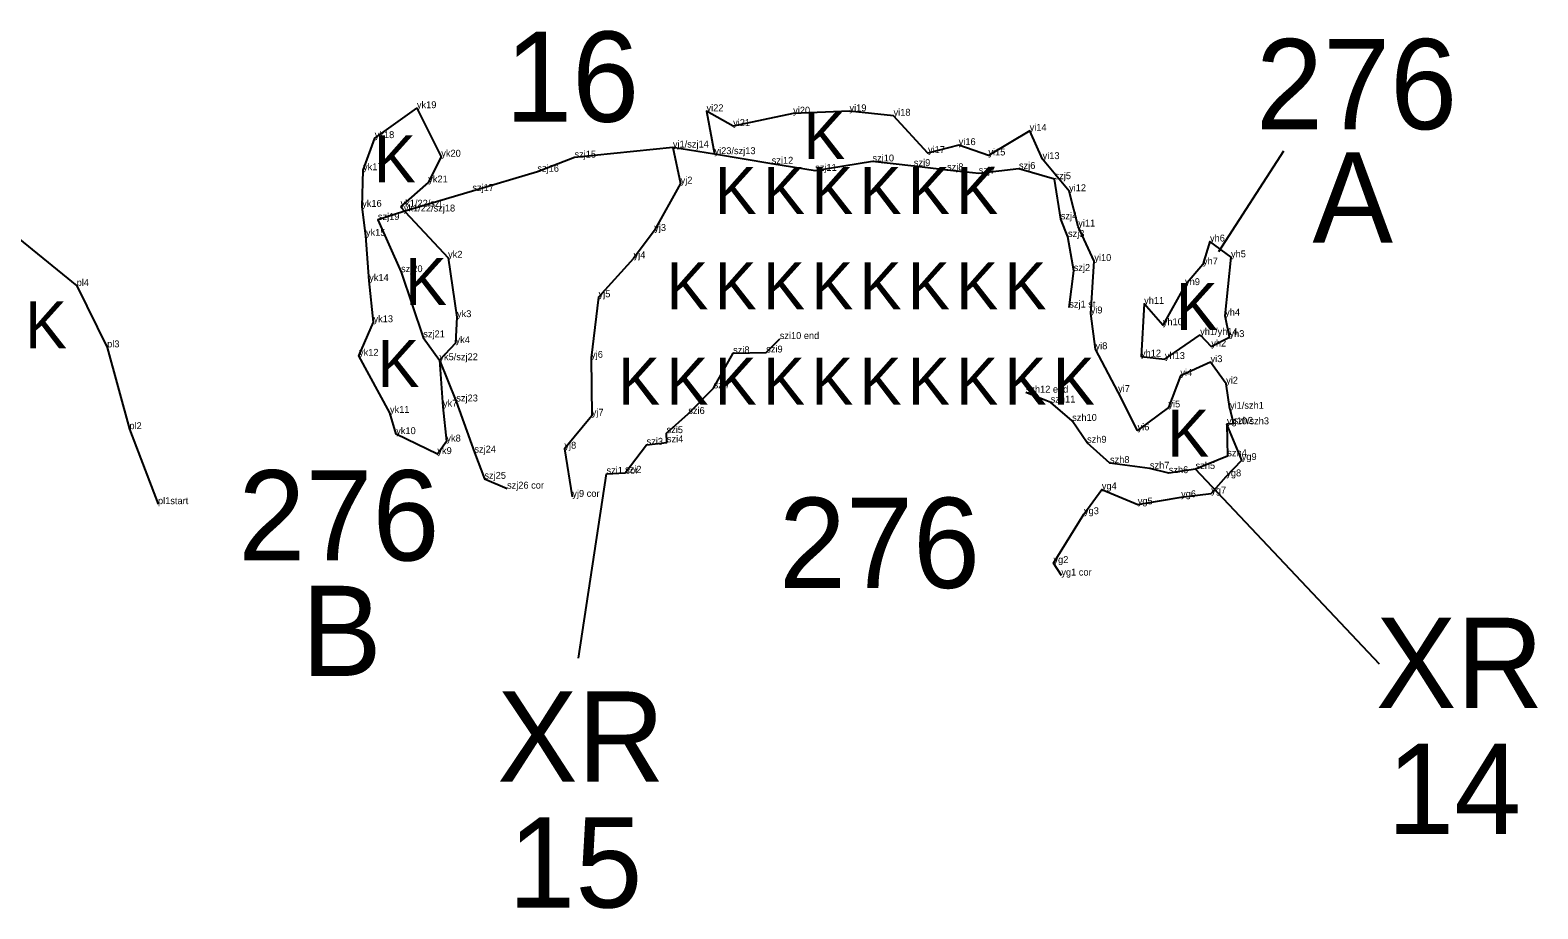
# Model space of a CAD drawing. Extents: x 2072529 to 2268812, y 436423 to 470008.
# Drawn here: x 2234269 to 2235362, y 437440 to 438077 of the extents above; entities that cross this region are included whole.
import ezdxf

# ---------------------------------------------------------------- set-up
doc = ezdxf.new("R2010")
doc.units = 0
for name, color, linetype in [('Old_Level_10', 7, 'Continuous'), ('Old_Level_20', 7, 'Continuous'), ('Old_Level_52', 7, 'Continuous'), ('Old_Level_55', 7, 'Continuous'), ('Old_Level_60', 7, 'Continuous'), ('Old_Level_62', 7, 'Continuous')]:
    doc.layers.add(name, color=color, linetype=linetype)

msp = doc.modelspace()

# ---------------------------------------------------------------- linework, layer by layer
at = {"layer": 'Old_Level_10'}
for points in [[(2235022.15, 437875.772), (2235025.327, 437902.254), (2235021.192, 437926.912), (2235015.992, 437939.663), (2235011.459, 437968.738), (2234985.669, 437976.204), (2234956.556, 437972.832), (2234933.554, 437975.202), (2234909.517, 437978.237), (2234879.528, 437981.569), (2234838.013, 437974.72), (2234806.501, 437979.899), (2234765.07, 437986.858), (2234734.927, 437991.638), (2234663.634, 437984.333)], [(2234663.634, 437984.333), (2234636.744, 437974.103), (2234589.636, 437960.148), (2234539.989, 437945.334), (2234521.191, 437939.225), (2234537.967, 437901.417), (2234537.967, 437901.417), (2234554.11, 437854.212), (2234565.741, 437837.655), (2234578.009, 437807.788), (2234591.124, 437770.801), (2234598.353, 437751.778), (2234614.765, 437744.67)], [(2234686.83, 437755.439), (2234700.252, 437756.17), (2234715.876, 437776.426), (2234730.592, 437778.188), (2234730.315, 437784.863), (2234746.096, 437798.752), (2234764.454, 437817.355), (2234778.551, 437842.644), (2234802.551, 437843.25), (2234812.336, 437853.021)], [(2235138.563, 437802.471), (2235141.179, 437791.607), (2235136.336, 437791.232), (2235136.644, 437768.164), (2235113.636, 437758.868), (2235094.216, 437755.875), (2235080.539, 437759.128), (2235051.628, 437763.196), (2235034.996, 437777.892), (2235024.223, 437793.719), (2235008.663, 437806.995), (2234990.571, 437814.172)]]:
    msp.add_lwpolyline(points, dxfattribs=at)
at = {"layer": 'Old_Level_20'}
for p, q in [((2234549.462, 438020.14), (2234549.462, 438020.14)), ((2234759.309, 438017.899), (2234759.309, 438017.899)), ((2234822.071, 438016.169), (2234822.071, 438016.169)), ((2234862.899, 438017.892), (2234862.899, 438017.892)), ((2234894.802, 438014.665), (2234894.802, 438014.665)), ((2234518.925, 437998.451), (2234518.925, 437998.451)), ((2234778.554, 438007.23), (2234778.554, 438007.23)), ((2234993.448, 438003.763), (2234993.448, 438003.763)), ((2234734.927, 437991.638), (2234734.927, 437991.638)), ((2234765.07, 437986.858), (2234765.07, 437986.858)), ((2234919.763, 437987.653), (2234919.763, 437987.653)), ((2234942.011, 437993.39), (2234942.011, 437993.39)), ((2234567.121, 437985.001), (2234567.121, 437985.001)), ((2234663.634, 437984.333), (2234663.634, 437984.333)), ((2234806.501, 437979.899), (2234806.501, 437979.899)), ((2234879.528, 437981.569), (2234879.528, 437981.569)), ((2234909.517, 437978.237), (2234909.517, 437978.237)), ((2234963.543, 437985.902), (2234963.543, 437985.902)), ((2234985.669, 437976.204), (2234985.669, 437976.204)), ((2235002.799, 437983.256), (2235002.799, 437983.256)), ((2234510.467, 437975.219), (2234510.467, 437975.219)), ((2234557.684, 437966.361), (2234557.684, 437966.361)), ((2234636.744, 437974.103), (2234636.744, 437974.103)), ((2234740.535, 437965.54), (2234740.535, 437965.54)), ((2234838.013, 437974.72), (2234838.013, 437974.72)), ((2234933.554, 437975.202), (2234933.554, 437975.202)), ((2234956.556, 437972.832), (2234956.556, 437972.832)), ((2235011.459, 437968.738), (2235011.459, 437968.738)), ((2234589.636, 437960.148), (2234589.636, 437960.148)), ((2235021.981, 437959.999), (2235021.981, 437959.999)), ((2234509.818, 437948.702), (2234509.818, 437948.702)), ((2234537.63, 437948.816), (2234537.63, 437948.816)), ((2234539.989, 437945.334), (2234539.989, 437945.334)), ((2234521.191, 437939.225), (2234521.191, 437939.225)), ((2235015.992, 437939.663), (2235015.992, 437939.663)), ((2235028.621, 437934.464), (2235028.621, 437934.464)), ((2234512.538, 437927.728), (2234512.538, 437927.728)), ((2234721.404, 437931.218), (2234721.404, 437931.218)), ((2235021.192, 437926.912), (2235021.192, 437926.912)), ((2235124.081, 437923.587), (2235124.081, 437923.587)), ((2234572.047, 437911.831), (2234572.047, 437911.831)), ((2234706.445, 437911.397), (2234706.445, 437911.397)), ((2235139.3, 437912.147), (2235139.3, 437912.147)), ((2234537.967, 437901.417), (2234537.967, 437901.417)), ((2235025.327, 437902.254), (2235025.327, 437902.254)), ((2235040.267, 437909.469), (2235040.267, 437909.469)), ((2235118.998, 437906.971), (2235118.998, 437906.971)), ((2234302.955, 437891.465), (2234302.955, 437891.465)), ((2234514.937, 437895.051), (2234514.937, 437895.051)), ((2235106.017, 437892.022), (2235106.017, 437892.022)), ((2234681.088, 437883.21), (2234681.088, 437883.21)), ((2235076.351, 437878.443), (2235076.351, 437878.443)), ((2234578.495, 437868.837), (2234578.495, 437868.837)), ((2235022.15, 437875.772), (2235022.15, 437875.772)), ((2235037.635, 437871.513), (2235037.635, 437871.513)), ((2235135.049, 437869.864), (2235135.049, 437869.864)), ((2234518.046, 437865.145), (2234518.046, 437865.145)), ((2235089.888, 437863.006), (2235089.888, 437863.006)), ((2235116.938, 437855.947), (2235116.938, 437855.947)), ((2234325.02, 437846.969), (2234325.02, 437846.969)), ((2234554.11, 437854.212), (2234554.11, 437854.212)), ((2234577.468, 437850.019), (2234577.468, 437850.019)), ((2234812.336, 437853.021), (2234812.336, 437853.021)), ((2235041.14, 437845.595), (2235041.14, 437845.595)), ((2235125.004, 437847.557), (2235125.004, 437847.557)), ((2235138.202, 437854.402), (2235138.202, 437854.402)), ((2234507.492, 437840.861), (2234507.492, 437840.861)), ((2234565.741, 437837.655), (2234565.741, 437837.655)), ((2234675.663, 437839.359), (2234675.663, 437839.359)), ((2234778.551, 437842.644), (2234778.551, 437842.644)), ((2234802.551, 437843.25), (2234802.551, 437843.25)), ((2235074.094, 437840.264), (2235074.094, 437840.264)), ((2235091.387, 437838.504), (2235091.387, 437838.504)), ((2235124.496, 437836.247), (2235124.496, 437836.247)), ((2235102.621, 437826.301), (2235102.621, 437826.301)), ((2234764.454, 437817.355), (2234764.454, 437817.355)), ((2234990.571, 437814.172), (2234990.571, 437814.172)), ((2235057.473, 437814.616), (2235057.473, 437814.616)), ((2235135.765, 437820.648), (2235135.765, 437820.648)), ((2234568.354, 437803.979), (2234568.354, 437803.979)), ((2234578.009, 437807.788), (2234578.009, 437807.788)), ((2235008.663, 437806.995), (2235008.663, 437806.995)), ((2235093.937, 437803.459), (2235093.937, 437803.459)), ((2235138.563, 437802.471), (2235138.563, 437802.471)), ((2234529.944, 437799.536), (2234529.944, 437799.536)), ((2234676.167, 437797.486), (2234676.167, 437797.486)), ((2234746.096, 437798.752), (2234746.096, 437798.752)), ((2235024.223, 437793.719), (2235024.223, 437793.719)), ((2235136.336, 437791.232), (2235136.336, 437791.232)), ((2235141.179, 437791.607), (2235141.179, 437791.607)), ((2234341.173, 437787.743), (2234341.173, 437787.743)), ((2234534.478, 437784.117), (2234534.478, 437784.117)), ((2234730.315, 437784.863), (2234730.315, 437784.863)), ((2235071.627, 437786.86), (2235071.627, 437786.86)), ((2234564.3, 437769.673), (2234564.3, 437769.673)), ((2234570.842, 437778.764), (2234570.842, 437778.764)), ((2234591.124, 437770.801), (2234591.124, 437770.801)), ((2234656.349, 437773.568), (2234656.349, 437773.568)), ((2234715.876, 437776.426), (2234715.876, 437776.426)), ((2234730.592, 437778.188), (2234730.592, 437778.188)), ((2235034.996, 437777.892), (2235034.996, 437777.892)), ((2235136.644, 437768.164), (2235136.644, 437768.164)), ((2235051.628, 437763.196), (2235051.628, 437763.196)), ((2235080.539, 437759.128), (2235080.539, 437759.128)), ((2235113.636, 437758.868), (2235113.636, 437758.868)), ((2235147.076, 437765.363), (2235147.076, 437765.363)), ((2234598.353, 437751.778), (2234598.353, 437751.778)), ((2234686.83, 437755.439), (2234686.83, 437755.439)), ((2234700.252, 437756.17), (2234700.252, 437756.17)), ((2235094.216, 437755.875), (2235094.216, 437755.875)), ((2235135.885, 437753.531), (2235135.885, 437753.531)), ((2234614.765, 437744.67), (2234614.765, 437744.67)), ((2234662.065, 437738.699), (2234662.065, 437738.699)), ((2235045.704, 437744.146), (2235045.704, 437744.146)), ((2235103.144, 437738.471), (2235103.144, 437738.471)), ((2235124.954, 437741.061), (2235124.954, 437741.061)), ((2234361.875, 437733.432), (2234361.875, 437733.432)), ((2235032.774, 437726.165), (2235032.774, 437726.165)), ((2235071.747, 437733.241), (2235071.747, 437733.241)), ((2235010.659, 437690.787), (2235010.659, 437690.787)), ((2235016.393, 437681.725), (2235016.393, 437681.725))]:
    msp.add_line(p, q, dxfattribs=at)
at = {"layer": 'Old_Level_52'}
for points in [[(2234537.63, 437948.816), (2234572.047, 437911.831), (2234578.495, 437868.837), (2234577.468, 437850.019), (2234565.741, 437837.655), (2234568.354, 437803.979), (2234570.842, 437778.764), (2234564.3, 437769.673), (2234534.478, 437784.117), (2234529.944, 437799.536), (2234507.492, 437840.861), (2234518.046, 437865.145), (2234514.937, 437895.051), (2234512.538, 437927.728), (2234509.818, 437948.702), (2234510.467, 437975.219), (2234518.925, 437998.451), (2234549.462, 438020.14), (2234567.121, 437985.001), (2234557.684, 437966.361)], [(2235116.938, 437855.947), (2235125.004, 437847.557), (2235138.202, 437854.402), (2235135.049, 437869.864), (2235139.3, 437912.147), (2235124.081, 437923.587), (2235118.998, 437906.971), (2235106.017, 437892.022), (2235089.888, 437863.006), (2235076.351, 437878.443), (2235074.094, 437840.264), (2235091.387, 437838.504)]]:
    msp.add_lwpolyline(points, close=True, dxfattribs=at)
for points in [[(2235138.563, 437802.471), (2235135.765, 437820.648), (2235124.496, 437836.247), (2235102.621, 437826.301), (2235093.937, 437803.459), (2235071.627, 437786.86), (2235057.473, 437814.616), (2235041.14, 437845.595), (2235037.635, 437871.513), (2235040.267, 437909.469), (2235028.621, 437934.464), (2235021.981, 437959.999), (2235002.799, 437983.256), (2234993.448, 438003.763), (2234963.543, 437985.902), (2234942.011, 437993.39), (2234919.763, 437987.653), (2234894.802, 438014.665), (2234862.899, 438017.892), (2234822.071, 438016.169), (2234778.554, 438007.23), (2234759.309, 438017.899), (2234765.07, 437986.858)], [(2234734.927, 437991.638), (2234740.535, 437965.54), (2234721.404, 437931.218), (2234706.445, 437911.397), (2234681.088, 437883.21), (2234675.663, 437839.359), (2234676.167, 437797.486), (2234656.349, 437773.568), (2234662.065, 437738.699)], [(2234249.981, 437934.732), (2234302.955, 437891.465), (2234325.02, 437846.969), (2234341.173, 437787.743), (2234361.875, 437733.432)], [(2235016.393, 437681.725), (2235010.659, 437690.787), (2235032.774, 437726.165), (2235045.704, 437744.146), (2235071.747, 437733.241), (2235103.144, 437738.471), (2235124.954, 437741.061), (2235135.885, 437753.531), (2235147.076, 437765.363), (2235136.336, 437791.232)]]:
    msp.add_lwpolyline(points, dxfattribs=at)
at = {"layer": 'Old_Level_62'}
for p, q in [((2235177.329, 437989.035), (2235130.314, 437916.092)), ((2235246.992, 437617.604), (2235113.636, 437758.868)), ((2234666.573, 437621.978), (2234686.83, 437755.439))]:
    msp.add_line(p, q, dxfattribs=at)

# ---------------------------------------------------------------- texts
at = {"layer": 'Old_Level_55'}
for p in [(2234829.509, 437983.281), (2234518.369, 437966.412), (2234765.251, 437943.557), (2234800.251, 437943.557), (2234835.251, 437943.557), (2234870.251, 437943.557), (2234905.251, 437943.557), (2234940.251, 437943.557), (2234540.861, 437877.693), (2234730.251, 437874.557), (2234765.251, 437874.557), (2234800.251, 437874.557), (2234835.251, 437874.557), (2234870.251, 437874.557), (2234905.251, 437874.557), (2234940.251, 437874.557), (2234975.251, 437874.557), (2235099.413, 437859.575), (2234265.577, 437846.244), (2234520.869, 437818.339), (2234695.251, 437805.557), (2234730.251, 437805.557), (2234765.251, 437805.557), (2234800.251, 437805.557), (2234835.251, 437805.557), (2234870.251, 437805.557), (2234905.251, 437805.557), (2234940.251, 437805.557), (2234975.251, 437805.557), (2235010.251, 437805.557), (2235093.165, 437767.732)]:
    msp.add_text('K', height=34, dxfattribs=at).set_placement(p)
at = {"layer": 'Old_Level_60'}
for s, p in [('yk19', (2234549.462, 438020.14)), ('yi22', (2234759.309, 438017.899)), ('yi20', (2234822.071, 438016.169)), ('yi19', (2234862.899, 438017.892)), ('yi18', (2234894.802, 438014.665)), ('yi21', (2234778.554, 438007.23)), ('yi14', (2234993.448, 438003.763)), ('yk18', (2234518.925, 437998.451)), ('yi16', (2234942.011, 437993.39)), ('yk20', (2234567.121, 437985.001)), ('szj15', (2234663.634, 437984.333)), ('yj1/szj14', (2234734.927, 437991.638)), ('yi23/szj13', (2234765.07, 437986.858)), ('szj10', (2234879.528, 437981.569)), ('yi17', (2234919.763, 437987.653)), ('yi15', (2234963.543, 437985.902)), ('yi13', (2235002.799, 437983.256)), ('yk17', (2234510.467, 437975.219)), ('szj16', (2234636.744, 437974.103)), ('szj12', (2234806.501, 437979.899)), ('szj11', (2234838.013, 437974.72)), ('szj9', (2234909.517, 437978.237)), ('szj8', (2234933.554, 437975.202)), ('szj7', (2234956.556, 437972.832)), ('szj6', (2234985.669, 437976.204)), ('yk21', (2234557.684, 437966.361)), ('szj17', (2234589.636, 437960.148)), ('yj2', (2234740.535, 437965.54)), ('szj5', (2235011.459, 437968.738)), ('yi12', (2235021.981, 437959.999)), ('yk16', (2234509.818, 437948.702)), ('yk1/22/szj', (2234537.63, 437948.816)), ('szj19', (2234521.191, 437939.225)), ('yk1/22/szj18', (2234539.989, 437945.334)), ('szj4', (2235015.992, 437939.663)), ('yk15', (2234512.538, 437927.728)), ('yj3', (2234721.404, 437931.218)), ('szj3', (2235021.192, 437926.912)), ('yi11', (2235028.621, 437934.464)), ('yh6', (2235124.081, 437923.587)), ('yk2', (2234572.047, 437911.831)), ('yj4', (2234706.445, 437911.397)), ('yi10', (2235040.267, 437909.469)), ('yh7', (2235118.998, 437906.971)), ('yh5', (2235139.3, 437912.147)), ('yk14', (2234514.937, 437895.051)), ('szj20', (2234537.967, 437901.417)), ('szj2', (2235025.327, 437902.254)), ('pl4', (2234302.955, 437891.465)), ('yj5', (2234681.088, 437883.21)), ('yh9', (2235106.017, 437892.022)), ('szj1 st', (2235022.15, 437875.772)), ('yh11', (2235076.351, 437878.443)), ('yk13', (2234518.046, 437865.145)), ('yk3', (2234578.495, 437868.837)), ('yi9', (2235037.635, 437871.513)), ('yh10', (2235089.888, 437863.006)), ('yh4', (2235135.049, 437869.864)), ('szj21', (2234554.11, 437854.212)), ('szi10 end', (2234812.336, 437853.021)), ('yh1/yh14', (2235116.938, 437855.947)), ('yh3', (2235138.202, 437854.402)), ('pl3', (2234325.02, 437846.969)), ('yk12', (2234507.492, 437840.861)), ('yk4', (2234577.468, 437850.019)), ('yj6', (2234675.663, 437839.359)), ('szi8', (2234778.551, 437842.644)), ('szi9', (2234802.551, 437843.25)), ('yi8', (2235041.14, 437845.595)), ('yh12', (2235074.094, 437840.264)), ('yh2', (2235125.004, 437847.557)), ('yk5/szj22', (2234565.741, 437837.655)), ('yh13', (2235091.387, 437838.504)), ('yi3', (2235124.496, 437836.247)), ('szi7', (2234764.454, 437817.355)), ('yi4', (2235102.621, 437826.301)), ('yi2', (2235135.765, 437820.648)), ('szj23', (2234578.009, 437807.788)), ('szh12 end', (2234990.571, 437814.172)), ('szh11', (2235008.663, 437806.995)), ('yi7', (2235057.473, 437814.616)), ('yk11', (2234529.944, 437799.536)), ('yk7', (2234568.354, 437803.979)), ('yj7', (2234676.167, 437797.486)), ('szi6', (2234746.096, 437798.752)), ('yi5', (2235093.937, 437803.459)), ('yi1/szh1', (2235138.563, 437802.471)), ('pl2', (2234341.173, 437787.743)), ('szi5', (2234730.315, 437784.863)), ('szh10', (2235024.223, 437793.719)), ('yi6', (2235071.627, 437786.86)), ('yg10/szh3', (2235136.336, 437791.232)), ('szh2', (2235141.179, 437791.607)), ('yk10', (2234534.478, 437784.117)), ('yk8', (2234570.842, 437778.764)), ('szi3', (2234715.876, 437776.426)), ('szi4', (2234730.592, 437778.188)), ('szh9', (2235034.996, 437777.892)), ('yk9', (2234564.3, 437769.673)), ('szj24', (2234591.124, 437770.801)), ('yj8', (2234656.349, 437773.568)), ('szh8', (2235051.628, 437763.196)), ('szh4', (2235136.644, 437768.164)), ('yg9', (2235147.076, 437765.363)), ('szj25', (2234598.353, 437751.778)), ('szi1 cor', (2234686.83, 437755.439)), ('szi2', (2234700.252, 437756.17)), ('szh7', (2235080.539, 437759.128)), ('szh6', (2235094.216, 437755.875)), ('szh5', (2235113.636, 437758.868)), ('yg8', (2235135.885, 437753.531)), ('szj26 cor', (2234614.765, 437744.67)), ('yg4', (2235045.704, 437744.146)), ('pl1start', (2234361.875, 437733.432)), ('yj9 cor', (2234662.065, 437738.699)), ('yg5', (2235071.747, 437733.241)), ('yg6', (2235103.144, 437738.471)), ('yg7', (2235124.954, 437741.061)), ('yg3', (2235032.774, 437726.165)), ('yg2', (2235010.659, 437690.787)), ('yg1 cor', (2235016.393, 437681.725))]:
    msp.add_text(s, height=5, dxfattribs=at).set_placement(p)
at = {"layer": 'Old_Level_62'}
for s, p in [('16', (2234613.328, 438010.307)), ('276', (2235157.387, 438004.91)), ('A', (2235198.325, 437922.875)), ('276', (2234420.047, 437692.641)), ('276', (2234811.696, 437672.754)), ('B', (2234465.715, 437609.029)), ('XR', (2235244.293, 437585.861)), ('XR', (2234607.595, 437532.499)), ('14', (2235252.341, 437494.713)), ('15', (2234615.643, 437441.351))]:
    msp.add_text(s, height=65.34, dxfattribs=at).set_placement(p)

doc.saveas('drawing.dxf')
